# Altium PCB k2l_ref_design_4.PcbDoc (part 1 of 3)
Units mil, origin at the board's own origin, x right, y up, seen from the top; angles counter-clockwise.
Board outline 8000 x 6000 mil, 2 copper layers (Top Layer, Bottom Layer), stack 62 mil thick; 620 components, 466 nets, 2754 pads, 0 vias.
Unrouted connection lines stored in the file: 183.
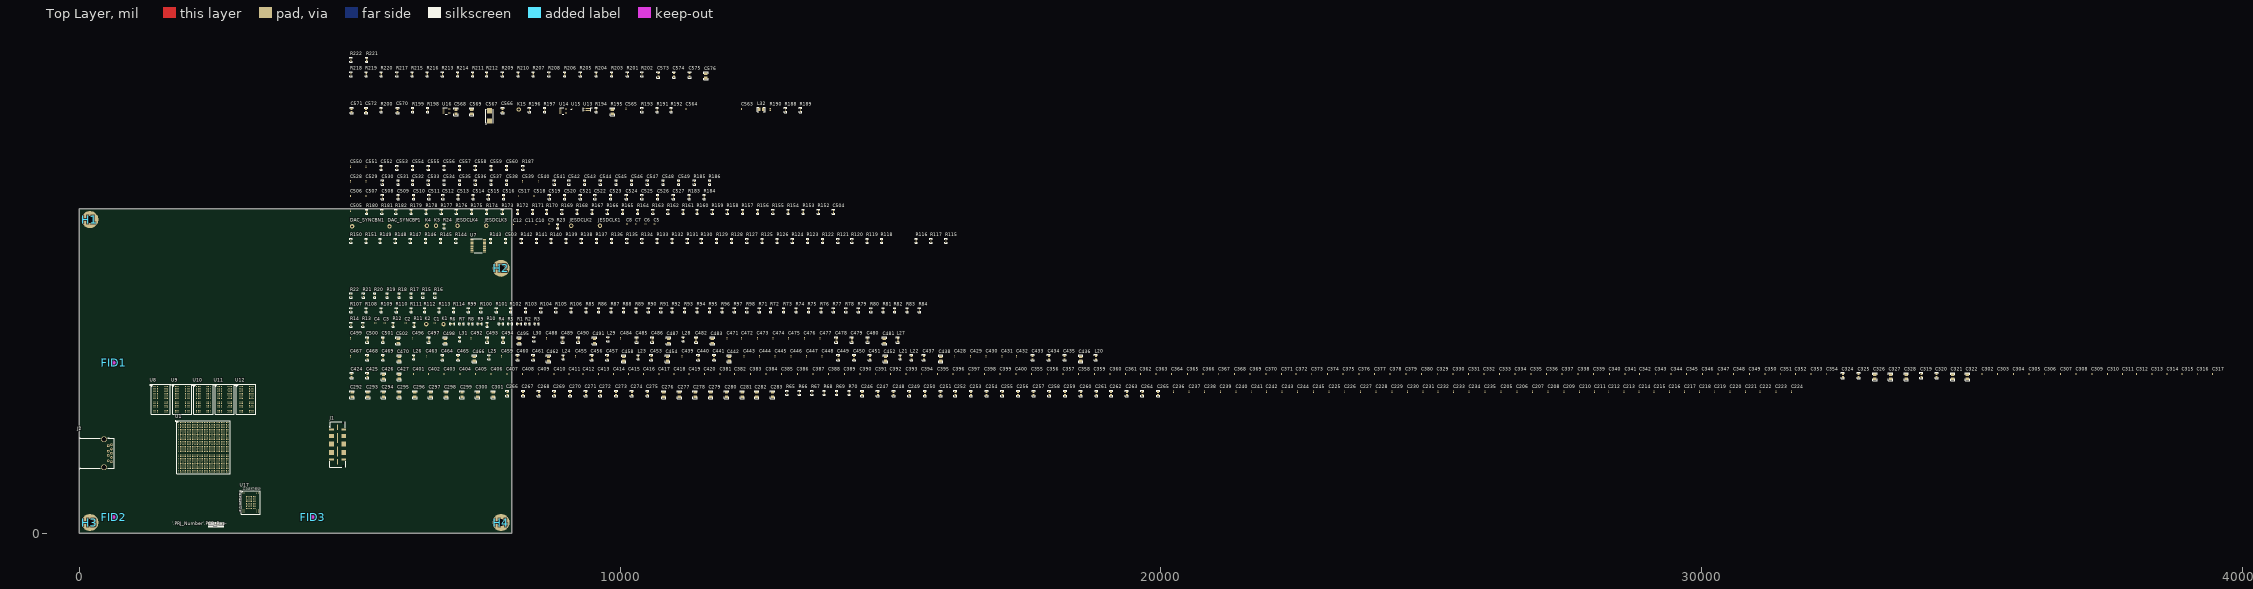
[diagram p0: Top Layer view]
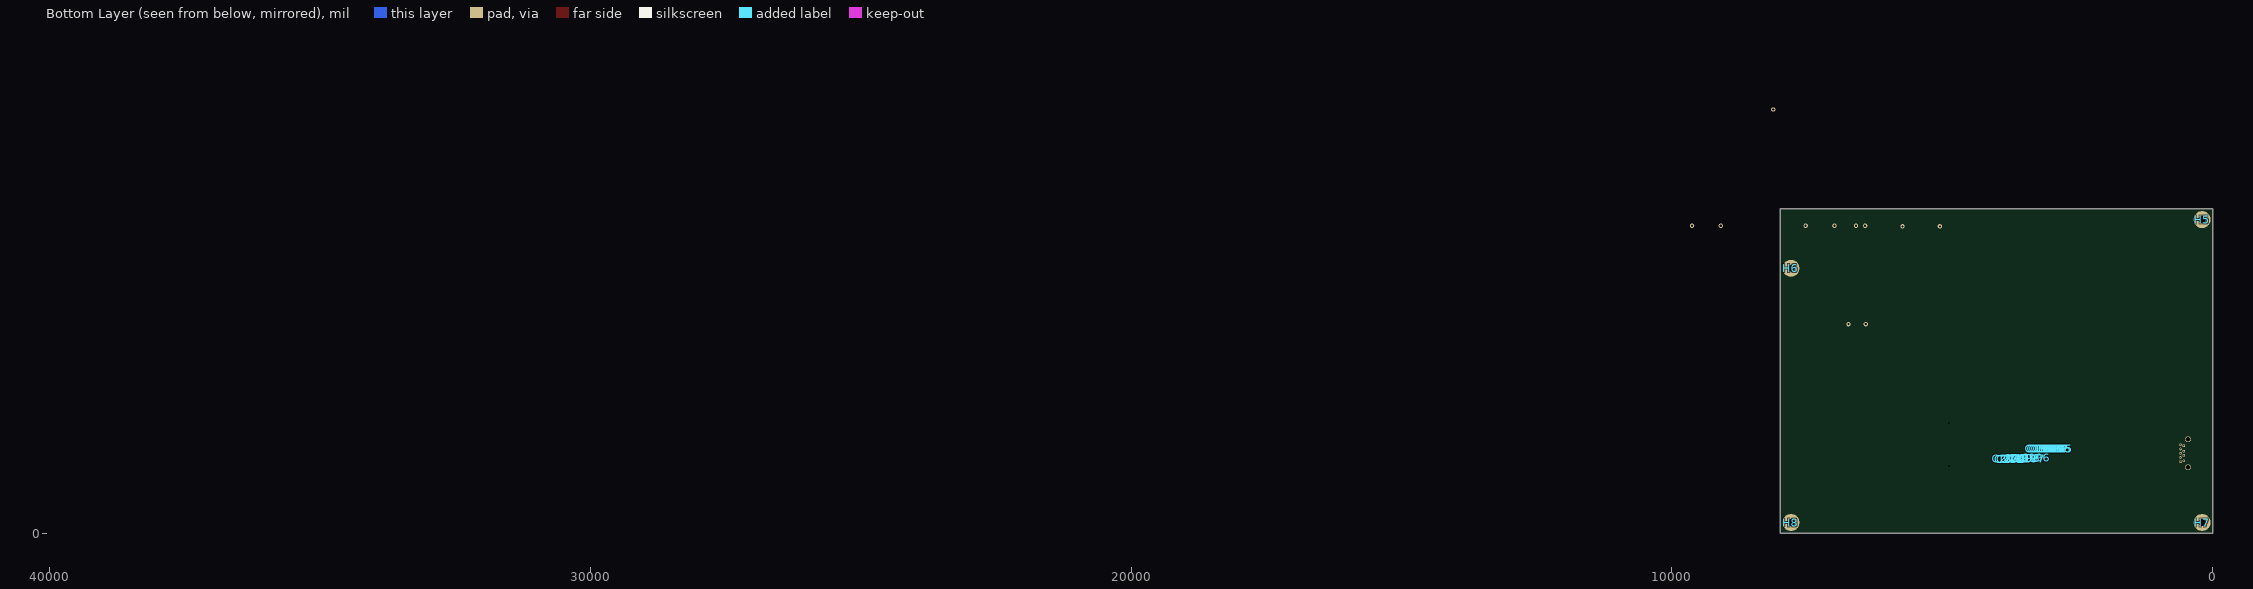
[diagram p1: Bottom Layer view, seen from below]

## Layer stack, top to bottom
Top Solder: solder mask 0.4, Solder Resist, Dk 3.5
Top Layer: signal copper 1.4
Dielectric1: core 59.2, FR-4, Dk 4.8
Bottom Layer: signal copper 1.4
Bottom Solder: solder mask 0.4, Solder Resist, Dk 3.5

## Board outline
0,0 0,6000 8000,6000 8000,0

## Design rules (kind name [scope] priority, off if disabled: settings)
AcuteAngle [All] p1: minimum=4.50000000000000E+0001 checktracksonly=FALSE
AssemblyTestPointUsage [All] p1: valid=2
BoardOutlineClearance BoardOutlineClearance_MountingHoles [OnCopper and InComponentClass('Mounting Holes')] p1: gap=40
BoardOutlineClearance BoardOutlineClearance_Poly [OnCopper and IsPoly] p2: gap=25
BoardOutlineClearance [OnCopper and Not InComponentClass('Logo') and not InComponentClass('FiducialMark') and not InRegion(1000,500,4000,800) and not InPoly] p3: gap=75
Clearance Clearance_Keepouts [((IsTrack Or IsArc) And Not InPoly) And IsFree and IsKeepOut vs ((IsTrack Or IsArc) And Not InPoly) And IsFree and IsKeepOut] p1: gap=0
Clearance Clearance_Poly [InPolygon] p2: gap=25
Clearance [All] p3: gap=7.87
ComponentClearance ComponentClearance_MountingHoles_FiducialMarks [InComponentClass('Mounting Holes') vs InComponentClass('FiducialMark')] p1: gap=50 collisioncheckmode=3 verticalgap=10 showdistances=FALSE
ComponentClearance ComponentClearance_Shunt [InComponentClass('Header') vs InComponentClass('Shunt')] p2: gap=0 collisioncheckmode=3 verticalgap=0 showdistances=FALSE
ComponentClearance ComponentClearance_Logo [InComponentClass('Logo')] p3: gap=50 collisioncheckmode=3 verticalgap=10 showdistances=FALSE
ComponentClearance ComponentClearance_ScrewToNut [(HasFootprint('NY PMS 440 0025 PH')) vs (HasFootprint('Keystone_1902C'))] p4: gap=5 collisioncheckmode=3 verticalgap=10 showdistances=FALSE
ComponentClearance ComponentClearance_MountingHoles [InComponentClass('Mounting Holes')] p5: gap=250 collisioncheckmode=3 verticalgap=100000 showdistances=FALSE
ComponentClearance ComponentClearance_SmallPassives [HasFootprint('0201*') or HasFootprint('0402*') or HasFootprint('0508') or HasFootprint('0603*') or HasFootprint('0612') or HasFootprint('0805*') or HasFootprint('0815*') or HasFootprint('0830*') or HasFootprint('1206*') or HasFootprint('1210*') or HasFootprint('1808*') or HasFootprint('1812*') or HasFootprint('1825*') or HasFootprint('2010*') or HasFootprint('2220*') or HasFootprint('2225*') or HasFootprint('2512*') or HasFootprint('2728*') or HasFootprint('3518*') vs HasFootprint('0201*') or HasFootprint('0402*') or HasFootprint('0508') or HasFootprint('0603*') or HasFootprint('0612') or HasFootprint('0805*') or HasFootprint('0815*') or HasFootprint('0830*') or HasFootprint('1206*') or HasFootprint('1210*') or HasFootprint('1808*') or HasFootprint('1812*') or HasFootprint('1825*') or HasFootprint('2010*') or HasFootprint('2220*') or HasFootprint('2225*') or HasFootprint('2512*') or HasFootprint('2728*') or HasFootprint('3518*')] p6: gap=14.96 collisioncheckmode=3 verticalgap=10 showdistances=FALSE
ComponentClearance ComponentClearance_THtoSMT [IsThruComponent vs IsSMTComponent] p7: gap=40 collisioncheckmode=3 verticalgap=30 showdistances=FALSE
ComponentClearance ComponentClearance_THtoTH [IsThruComponent vs IsThruComponent] p8: gap=30 collisioncheckmode=3 verticalgap=30 showdistances=FALSE
ComponentClearance [All] p9: gap=30 collisioncheckmode=3 verticalgap=10 showdistances=FALSE
DiffPairsRouting [All] p1: maxlimit=100 minlimit=10 mostfreqgap=10 toplayer_minwidth=15 toplayer_maxwidth=15 toplayer_prefwidth=15 bottomlayer_minwidth=15 bottomlayer_maxwidth=15 bottomlayer_prefwidth=15 maxuncoupledlength=1000
FabricationTestPointUsage TestPointUsage [All] p1: valid=2 allowmultiple=FALSE
FabricationTestpoint Testpoint [All] p1: side=3 testpointundercomponent=TRUE minsize=40 maxsize=100 preferedsize=60 minholesize=0 maxholesize=40 preferedholesize=32 testpointgrid=1 allowsidetop=TRUE allowsidebottom=TRUE usegrid=TRUE gridtolerance=0.01
FanoutControl Fanout_LCC [IsLCC] p1: bgadir=Out bgaviamode=Centered fanoutstyle=Auto fanoutdirection=Alternating viagrid=1 // Fanout_LCC (Default Rule)
FanoutControl Fanout_BGA [IsBGA] p2: bgadir=Out bgaviamode=Centered fanoutstyle=Auto fanoutdirection=Alternating viagrid=1 // Fanout_BGA (Default Rule)
FanoutControl Fanout_Default [All] p4: bgadir=Out bgaviamode=Centered fanoutstyle=Auto fanoutdirection=Alternating viagrid=1 // Fanout_Default (Default Rule)
FanoutControl Fanout_Small [(CompPinCount < 5)] p5: bgadir=Out bgaviamode=Centered fanoutstyle=Auto fanoutdirection=OutThenIn viagrid=1 // Fanout_Small (Default Rule)
HoleSize [All] p1: absolutevalues=TRUE maxlimit=251 minlimit=7.87 maxpercent=80.000 minpercent=20.000
MinimumAnnularRing MinimumAnnularRing_ThermalPadVias [IsVia and InAnyComponent] p1: minimumring=5.91
MinimumAnnularRing [All] p2: minimumring=8
MinimumSolderMaskSliver MinimumSolderMaskSliver_Logo [InComponentClass('Logo') vs InComponentClass('Logo')] p1: minsoldermaskwidth=0.7
MinimumSolderMaskSliver [All] p2: minsoldermaskwidth=3.94
PlaneConnect [All] p1: planeconnectstyle=Relief reliefexpansion=10 reliefentries=4 reliefconductorwidth=10 reliefairgap=10
PolygonConnect [All] p1: connectstyle=Relief reliefconductorwidth=10 reliefentries=4 polygonreliefangle="90 Angle" airgapwidth=10
RoutingVias ThermalPadVias [IsVia and InAnyComponent] p1: holewidth=7.87 width=19.68 viastyle="Through Hole" minholewidth=7.87 minwidth=19.68 maxholewidth=12.99 maxwidth=23.62
RoutingVias [All] p2: holewidth=16 width=34 viastyle="Through Hole" minholewidth=7.87 minwidth=26 maxholewidth=40 maxwidth=65
SilkToBoardRegionClearance [Not ((IsComment or IsDesignator) And (Hide <> 'False')) and not InRegion(1000,500,4000,800)] p1:
SilkToSilkClearance SilkToSilkClearance_Pb-FreeLogo [(HasFootprint('Pb-Free_Overlay_Medium') OR HasFootprint('Pb-Free_Overlay_Small')) vs (HasFootprint('Pb-Free_Overlay_Medium') OR HasFootprint('Pb-Free_Overlay_Small'))] p1: silktosilkclearance=0
SilkToSilkClearance [All] p2: silktosilkclearance=4
SilkToSolderMaskClearance SilkToComponentPadClearance [IsPad and InAnycomponent] p1: minsilkscreentomaskgap=5 clearancetoexposedcopper=TRUE
SilkToSolderMaskClearance "Silk to Solder Mask Opening" [All] p2: minsilkscreentomaskgap=4 clearancetoexposedcopper=FALSE
SolderMaskExpansion [All] p1: expansion=1.97
Width [All] p1: maxlimit=100 minlimit=6 preferedwidth=10 checkconnectedcopper=TRUE
15 further rules are at their usual default settings.

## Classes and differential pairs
component class "Mounting Holes": H1 H2 H3 H4
component class EVM_Hardware: FID1 FID2 FID3 H1 H2 H3 H4 H5 H6 H7 H8
component class FiducialMark: FID1 FID2 FID3
component class k2l_soc_01: U1
component class k2l_soc_02: C185 C186 C187 C188 C189 C190 C191 C192 C193 C194 C195 C196 C197 C198 C199 C200 C201 C202 C203 C204 C205 C206 C207 C208 C209 C210 C211 C212 C213 C214 C215 C216 C217 C218 C219 C220 C221 C222 C223 C224 C225 C226 C227 C228 C229 C230 C231 C232 C233 C234 C235 C236 C237 C238 C239 C240 C241 C242 C243 C244 C245 C246 C247 C248 C249 C250 C251 C252 C253 C254 C255 C256 C257 C258 C259 C260 C261 C262 C263 C264 C265 C266 C267 C268 C269 C270 C271 C272 C273 C274 C275 C276 C277 C278 C279 C280 C281 C282 C283 C284 C285 C286 C287 C288 C289 C290 C291 C292 C293 C294 C295 C296 C297 C298 C299 C300 C301 R65 R66 R67 R68 R69 R70
component class k2l_soc_03_1: C428 C429 C430 C431 C432 C433 C434 C435 C436 C437 C438 C439 C440 C441 C442 C443 C444 C445 C446 C447 C448 C449 C450 C451 C452 C453 C454 C455 C456 C457 C458 C459 C460 C461 C462 C463 C464 C465 C466 C467 C468 C469 C470 L20 L21 L22 L23 L24 L25 L26
component class k2l_soc_03: C302 C303 C304 C305 C306 C307 C308 C309 C310 C311 C312 C313 C314 C315 C316 C317 C318 C319 C320 C321 C322 C323 C324 C325 C326 C327 C328 C329 C330 C331 C332 C333 C334 C335 C336 C337 C338 C339 C340 C341 C342 C343 C344 C345 C346 C347 C348 C349 C350 C351 C352 C353 C354 C355 C356 C357 C358 C359 C360 C361 C362 C363 C364 C365 C366 C367 C368 C369 C370 C371 C372 C373 C374 C375 C376 C377 C378 C379 C380 C381 C382 C383 C384 C385 C386 C387 C388 C389 C390 C391 C392 C393 C394 C395 C396 C397 C398 C399 C400 C401 C402 C403 C404 C405 C406 C407 C408 C409 C410 C411 C412 C413 C414 C415 C416 C417 C418 C419 C420 C421 C422 C423 C424 C425 C426 C427
component class k2l_soc_04: C471 C472 C473 C474 C475 C476 C477 C478 C479 C480 C481 C482 C483 C484 C485 C486 C487 C488 C489 C490 C491 C492 C493 C494 C495 C496 C497 C498 C499 C500 C501 C502 L27 L28 L29 L30 L31
component class k2l_soc_05: C1 C2 C3 C4 K1 K2 R1 R2 R3 R4 R5 R6 R7 R8 R9 R10 R11 R12 R13 R14
component class k2l_soc_06_1: R15 R16 R17 R18 R19 R20 R21 R22
component class k2l_soc_06: R71 R72 R73 R74 R75 R76 R77 R78 R79 R80 R81 R82 R83 R84 R85 R86 R87 R88 R89 R90 R91 R92 R93 R94 R95 R96 R97 R98 R99 R100 R101 R102 R103 R104 R105 R106 R107 R108 R109 R110 R111 R112 R113 R114
component class k2l_soc_07: C503 J1 R115 R116 R117 R118 R119 R120 R121 R122 R123 R124 R125 R126 R127 R128 R129 R130 R131 R132 R133 R134 R135 R136 R137 R138 R139 R140 R141 R142 R143 R144 R145 R146 R147 R148 R149 R150 R151 U7
component class k2l_soc_08: C5 C6 C7 C8 C9 C10 C11 C12 DAC_SYNCBN1 DAC_SYNCBP1 JESDCLK1 JESDCLK2 JESDCLK3 JESDCLK4 K3 K4 R23 R24
component class k2l_soc_09_2: C506 C507 C508 C509 C510 C511 C512 C513 C514 C515 C516 C517 C518 C519 C520 C521 C522 C523 C524 C525 C526 C527 R183 R184 U8 U9
component class k2l_soc_09_3: C528 C529 C530 C531 C532 C533 C534 C535 C536 C537 C538 C539 C540 C541 C542 C543 C544 C545 C546 C547 C548 C549 R185 R186 U10 U11
component class k2l_soc_09_4: C550 C551 C552 C553 C554 C555 C556 C557 C558 C559 C560 R187 U12
component class k2l_soc_09: C504 C505 R152 R153 R154 R155 R156 R157 R158 R159 R160 R161 R162 R163 R164 R165 R166 R167 R168 R169 R170 R171 R172 R173 R174 R175 R176 R177 R178 R179 R180 R181 R182
component class k2l_soc_10: C561 C562 C563 C564 C565 C566 C567 C568 C569 C570 C571 C572 J2 K15 L32 R188 R189 R190 R191 R192 R193 R194 R195 R196 R197 R198 R199 R200 U13 U14 U15 U16
component class k2l_soc_13: C573 C574 C575 C576 R201 R202 R203 R204 R205 R206 R207 R208 R209 R210 R211 R212 R213 R214 R215 R216 R217 R218 R219 R220 U17
component class k2l_soc_14: R221 R222
net class K2L_DDR3A[15..0]: K2L_DDR3A0 K2L_DDR3A1 K2L_DDR3A2 K2L_DDR3A3 K2L_DDR3A4 K2L_DDR3A5 K2L_DDR3A6 K2L_DDR3A7 K2L_DDR3A8 K2L_DDR3A9 K2L_DDR3A10 K2L_DDR3A11 K2L_DDR3A12 K2L_DDR3A13 K2L_DDR3A14 K2L_DDR3A15
net class K2L_DDR3CB[7..0]: K2L_DDR3CB0 K2L_DDR3CB1 K2L_DDR3CB2 K2L_DDR3CB3 K2L_DDR3CB4 K2L_DDR3CB5 K2L_DDR3CB6 K2L_DDR3CB7
net class K2L_DDR3D[63..0]: K2L_DDR3D0 K2L_DDR3D1 K2L_DDR3D2 K2L_DDR3D3 K2L_DDR3D4 K2L_DDR3D5 K2L_DDR3D6 K2L_DDR3D7 K2L_DDR3D8 K2L_DDR3D9 K2L_DDR3D10 K2L_DDR3D11 K2L_DDR3D12 K2L_DDR3D13 K2L_DDR3D14 K2L_DDR3D15 K2L_DDR3D16 K2L_DDR3D17 K2L_DDR3D18 K2L_DDR3D19 K2L_DDR3D20 K2L_DDR3D21 K2L_DDR3D22 K2L_DDR3D23 K2L_DDR3D24 K2L_DDR3D25 K2L_DDR3D26 K2L_DDR3D27 K2L_DDR3D28 K2L_DDR3D29 K2L_DDR3D30 K2L_DDR3D31 K2L_DDR3D32 K2L_DDR3D33 K2L_DDR3D34 K2L_DDR3D35 K2L_DDR3D36 K2L_DDR3D37 K2L_DDR3D38 K2L_DDR3D39 K2L_DDR3D40 K2L_DDR3D41 K2L_DDR3D42 K2L_DDR3D43 K2L_DDR3D44 K2L_DDR3D45 K2L_DDR3D46 K2L_DDR3D47 K2L_DDR3D48 K2L_DDR3D49 K2L_DDR3D50 K2L_DDR3D51 K2L_DDR3D52 K2L_DDR3D53 K2L_DDR3D54 K2L_DDR3D55 K2L_DDR3D56 K2L_DDR3D57 K2L_DDR3D58 K2L_DDR3D59 K2L_DDR3D60 K2L_DDR3D61 K2L_DDR3D62 K2L_DDR3D63
net class K2L_DFEIO[17..0]: K2L_DFEIO0 K2L_DFEIO1 K2L_DFEIO2 K2L_DFEIO3 K2L_DFEIO4 K2L_DFEIO5 K2L_DFEIO6 K2L_DFEIO7 K2L_DFEIO8 K2L_DFEIO9 K2L_DFEIO10 K2L_DFEIO11 K2L_DFEIO12 K2L_DFEIO13 K2L_DFEIO14 K2L_DFEIO15 K2L_DFEIO16 K2L_DFEIO17
net class K2L_GPIO[16..0]: K2L_GPIO0 K2L_GPIO1 K2L_GPIO2 K2L_GPIO3 K2L_GPIO4 K2L_GPIO5 K2L_GPIO6 K2L_GPIO7 K2L_GPIO8 K2L_GPIO9 K2L_GPIO10 K2L_GPIO11 K2L_GPIO12 K2L_GPIO13 K2L_GPIO14 K2L_GPIO15 K2L_GPIO16 K2L_GPIO17 K2L_GPIO18 K2L_GPIO19 K2L_GPIO20 K2L_GPIO21 K2L_GPIO22 K2L_GPIO23 K2L_GPIO24 K2L_GPIO26 K2L_GPIO27 K2L_GPIO28 K2L_GPIO29 K2L_GPIO30 K2L_GPIO31 K2L_GPIO32
net class Undefined: GND K2L_DDR3RZQ0 K2L_DDR3RZQ1 K2L_DDR3RZQ2 K2L_DDR3VREF K2L_JESD_RXN0 K2L_JESD_RXN0_CAP K2L_JESD_RXN1 K2L_JESD_RXN1_CAP K2L_JESD_RXP0 K2L_JESD_RXP0_CAP K2L_JESD_RXP1 K2L_JESD_RXP1_CAP K2L_JESD_TXN0 K2L_JESD_TXN1 K2L_JESD_TXN2 K2L_JESD_TXN3 K2L_JESD_TXP0 K2L_JESD_TXP1 K2L_JESD_TXP2 K2L_JESD_TXP3 K2L_SERDES0_REF K2L_SERDES1_REF NetR195_2

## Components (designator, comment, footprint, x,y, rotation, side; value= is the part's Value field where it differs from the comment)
C1 "C0603X5R0J104K030BC" 0201 6578,3886 r0 top
C2 "C0603X5R0J104K030BC" 0201 6038,3886 r0 top
C3 "C0603X5R0J104K030BC" 0201 5648,3886 r0 top
C4 "C0603X5R0J104K030BC" 0201 5478,3886 r0 top
C5 "CL03A104KP3NNNC" 0201L 10638,5716 r0 top
C6 "CL03A104KP3NNNC" 0201L 10468,5716 r0 top
C7 "CL03A104KP3NNNC" 0201L 10298,5716 r0 top
C8 "CL03A104KP3NNNC" 0201L 10128,5716 r0 top
C9 "CL03A104KP3NNNC" 0201L 8688,5716 r0 top
C10 "CL03A104KP3NNNC" 0201L 8448,5696 r90 top
C11 "CL03A104KP3NNNC" 0201L 8248,5696 r90 top
C12 "CL03A104KP3NNNC" 0201L 8028,5696 r90 top
C185 "GRM033R70J103KA01D" 0201 2846.46,1562.99 r90 bottom
C186 "GRM033R70J103KA01D" 0201 2877.95,1562.99 r90 bottom
C187 "GRM033R70J103KA01D" 0201 2913.39,1562.99 r90 bottom
C188 "GRM033R70J103KA01D" 0201 2948.82,1562.99 r90 bottom
C189 "GRM033R70J103KA01D" 0201 2984.25,1562.99 r90 bottom
C190 "GRM033R70J103KA01D" 0201 3019.69,1562.99 r90 bottom
C191 "GRM033R70J103KA01D" 0201 3055.12,1562.99 r90 bottom
C192 "GRM033R70J103KA01D" 0201 3090.55,1562.99 r90 bottom
C193 "GRM033R70J103KA01D" 0201 3125.98,1562.99 r90 bottom
C194 "GRM033R70J103KA01D" 0201 3161.42,1562.99 r90 bottom
C195 "GRM033R70J103KA01D" 0201 3196.85,1562.99 r90 bottom
C196 "GRM033R70J103KA01D" 0201 3263.78,1396.26 r90 bottom
C197 "GRM033R70J103KA01D" 0201 3358.27,1376.57 r90 bottom
C198 "GRM033R70J103KA01D" 0201 3448.82,1384.45 r90 bottom
C199 "GRM033R70J103KA01D" 0201 3519.69,1384.45 r90 bottom
C200 "GRM033R70J103KA01D" 0201 3590.55,1392.32 r90 bottom
C201 "GRM033R70J103KA01D" 0201 3657.48,1376.57 r90 bottom
C202 "GRM033R70J103KA01D" 0201 3724.41,1372.64 r90 bottom
C203 "GRM033R70J103KA01D" 0201 3767.72,1368.7 r90 bottom
C204 "GRM033R70J103KA01D" 0201 3814.96,1380.51 r90 bottom
C205 "GRM033R60J223KE01D" 0201 26288,2616 r90 top
C206 "GRM033R60J223KE01D" 0201 26578,2616 r90 top
C207 "GRM033R60J223KE01D" 0201 26868,2616 r90 top
C208 "GRM033R60J223KE01D" 0201 27158,2616 r90 top
C209 "GRM033R60J223KE01D" 0201 27448,2616 r90 top
C210 "GRM033R60J223KE01D" 0201 27738,2616 r90 top
C211 "GRM033R60J223KE01D" 0201 28018,2616 r90 top
C212 "GRM033R60J223KE01D" 0201 28278,2616 r90 top
C213 "GRM033R60J223KE01D" 0201 28558,2616 r90 top
C214 "GRM033R60J223KE01D" 0201 28838,2616 r90 top
C215 "GRM033R60J223KE01D" 0201 29118,2616 r90 top
C216 "GRM033R60J223KE01D" 0201 29398,2616 r90 top
C217 "GRM033R60J223KE01D" 0201 29678,2616 r90 top
C218 "GRM033R60J223KE01D" 0201 29958,2616 r90 top
C219 "GRM033R60J223KE01D" 0201 30238,2616 r90 top
C220 "GRM033R60J223KE01D" 0201 30518,2616 r90 top
C221 "GRM033R60J223KE01D" 0201 30808,2616 r90 top
C222 "GRM033R60J223KE01D" 0201 31078,2616 r90 top
C223 "GRM033R60J223KE01D" 0201 31368,2616 r90 top
C224 "GRM033R60J223KE01D" 0201 31658,2616 r90 top
C225 "GRM033R60J473KE19D" 0201 23108,2616 r90 top
C226 "GRM033R60J473KE19D" 0201 23398,2616 r90 top
C227 "GRM033R60J473KE19D" 0201 23688,2616 r90 top
C228 "GRM033R60J473KE19D" 0201 23978,2616 r90 top
C229 "GRM033R60J473KE19D" 0201 24268,2616 r90 top
C230 "GRM033R60J473KE19D" 0201 24558,2616 r90 top
C231 "GRM033R60J473KE19D" 0201 24848,2616 r90 top
C232 "GRM033R60J473KE19D" 0201 25118,2616 r90 top
C233 "GRM033R60J473KE19D" 0201 25408,2616 r90 top
C234 "GRM033R60J473KE19D" 0201 25698,2616 r90 top
C235 "GRM033R60J473KE19D" 0201 25988,2616 r90 top
C236 "GRM033R60J104KE19D" 0201_033 20228,2616 r90 top
C237 "GRM033R60J104KE19D" 0201_033 20518,2616 r90 top
C238 "GRM033R60J104KE19D" 0201_033 20808,2616 r90 top
C239 "GRM033R60J104KE19D" 0201_033 21098,2616 r90 top
C240 "GRM033R60J104KE19D" 0201_033 21388,2616 r90 top
C241 "GRM033R60J104KE19D" 0201_033 21678,2616 r90 top
C242 "GRM033R60J104KE19D" 0201_033 21948,2616 r90 top
C243 "GRM033R60J104KE19D" 0201_033 22238,2616 r90 top
C244 "GRM033R60J104KE19D" 0201_033 22528,2616 r90 top
C245 "GRM033R60J104KE19D" 0201_033 22818,2616 r90 top
C246 "GRM188R61A224KA01D" 0603 14478,2586 r90 top
C247 "GRM188R61A224KA01D" 0603 14768,2586 r90 top
C248 "GRM188R61A224KA01D" 0603 15058,2586 r90 top
C249 "GRM188R61A224KA01D" 0603 15348,2586 r90 top
C250 "GRM188R61A224KA01D" 0603 15638,2586 r90 top
C251 "GRM188R61A224KA01D" 0603 15928,2586 r90 top
C252 "GRM188R61A224KA01D" 0603 16198,2586 r90 top
C253 "GRM188R61A224KA01D" 0603 16488,2586 r90 top
C254 "GRM188R61A224KA01D" 0603 16778,2586 r90 top
C255 "GRM188R61A224KA01D" 0603 17068,2586 r90 top
C256 "GRM188R61A474KA61D" 0603 17358,2586 r90 top
C257 "GRM188R61A474KA61D" 0603 17648,2586 r90 top
C258 "GRM188R61A474KA61D" 0603 17938,2586 r90 top
C259 "GRM188R61A474KA61D" 0603 18228,2586 r90 top
C260 "GRM188R61A474KA61D" 0603 18518,2586 r90 top
C261 "GRM188R61A474KA61D" 0603 18808,2586 r90 top
C262 "GRM188R61A474KA61D" 0603 19078,2586 r90 top
C263 "GRM188R61A474KA61D" 0603 19368,2586 r90 top
C264 "GRM188R61A474KA61D" 0603 19658,2586 r90 top
C265 "GRM188R61A474KA61D" 0603 19948,2586 r90 top
C266 "GRM188R70J105KA01D" 0603 7918,2586 r90 top
C267 "GRM188R70J105KA01D" 0603 8208,2586 r90 top
C268 "GRM188R70J105KA01D" 0603 8498,2586 r90 top
C269 "GRM188R70J105KA01D" 0603 8788,2586 r90 top
C270 "GRM188R70J105KA01D" 0603 9078,2586 r90 top
C271 "GRM188R70J105KA01D" 0603 9368,2586 r90 top
C272 "GRM188R70J105KA01D" 0603 9638,2586 r90 top
C273 "GRM188R70J105KA01D" 0603 9928,2586 r90 top
C274 "GRM188R70J105KA01D" 0603 10218,2586 r90 top
C275 "GRM188R70J105KA01D" 0603 10508,2586 r90 top
C276 "GRM21BF50J106ZE01L" 0805_HV 10808,2566 r90 top
C277 "GRM21BF50J106ZE01L" 0805_HV 11098,2566 r90 top
C278 "GRM21BF50J106ZE01L" 0805_HV 11388,2566 r90 top
C279 "GRM21BF50J106ZE01L" 0805_HV 11678,2566 r90 top
C280 "GRM21BF50J106ZE01L" 0805_HV 11968,2566 r90 top
C281 "GRM21BF50J106ZE01L" 0805_HV 12258,2566 r90 top
C282 "GRM21BF50J106ZE01L" 0805_HV 12528,2566 r90 top
C283 "GRM21BF50J106ZE01L" 0805_HV 12818,2566 r90 top
C292 "GRM21BC80G226ME39L" 0805_HV 5048,2566 r90 top
C293 "GRM21BC80G226ME39L" 0805_HV 5338,2566 r90 top
C294 "GRM21BC80G226ME39L" 0805_HV 5628,2566 r90 top
C295 "GRM21BC80G226ME39L" 0805_HV 5918,2566 r90 top
C296 "GRM21BC80G226ME39L" 0805_HV 6208,2566 r90 top
C297 "GRM21BR60J476ME15L" 0805_HV 6498,2566 r90 top
C298 "GRM21BR60J476ME15L" 0805_HV 6788,2566 r90 top
C299 "GRM21BR60J476ME15L" 0805_HV 7078,2566 r90 top
C300 "GRM21BR60J476ME15L" 0805_HV 7368,2566 r90 top
C301 "GRM21BR60J476ME15L" 0805_HV 7658,2566 r90 top
C302 "GRM033R60J104KE19D" 0201_033 35178,2946 r90 top
C303 "GRM033R60J104KE19D" 0201_033 35468,2946 r90 top
C304 "GRM033R60J104KE19D" 0201_033 35758,2946 r90 top
C305 "GRM033R60J104KE19D" 0201_033 36048,2946 r90 top
C306 "GRM033R60J104KE19D" 0201_033 36338,2946 r90 top
C307 "GRM033R60J103KA01D" 0201 36628,2946 r90 top
C308 "GRM033R60J103KA01D" 0201 36918,2946 r90 top
C309 "GRM033R60J103KA01D" 0201 37208,2946 r90 top
C310 "GRM033R60J103KA01D" 0201 37498,2946 r90 top
C311 "GRM033R60J103KA01D" 0201 37778,2946 r90 top
C312 "GRM033R71C102KA01D" 0201 38038,2946 r90 top
C313 "GRM033R71C102KA01D" 0201 38318,2946 r90 top
C314 "GRM033R71C102KA01D" 0201 38598,2946 r90 top
C315 "GRM033R71C102KA01D" 0201 38878,2946 r90 top
C316 "GRM033R71C102KA01D" 0201 39158,2946 r90 top
C317 "GRM033R71C102KA01D" 0201 39438,2946 r90 top
C319 "GRM188R70J105KA01D" 0603 34058,2916 r90 top
C320 "GRM188R70J105KA01D" 0603 34338,2916 r90 top
C321 "GRM21BR70J106KE76L" 0805_HV 34638,2896 r90 top
C322 "GRM21BR70J106KE76L" 0805_HV 34908,2896 r90 top
C324 "GRM188R70J105KA01D" 0603 32608,2916 r90 top
C325 "GRM188R70J105KA01D" 0603 32898,2916 r90 top
C326 "GRM21BR70J106KE76L" 0805_HV 33198,2896 r90 top
C327 "GRM21BR70J106KE76L" 0805_HV 33488,2896 r90 top
C328 "GRM21BR70J106KE76L" 0805_HV 33778,2896 r90 top
C329 "GRM033R60J104KE19D" 0201_033 25108,2946 r90 top
C330 "GRM033R60J104KE19D" 0201_033 25398,2946 r90 top
C331 "GRM033R60J104KE19D" 0201_033 25688,2946 r90 top
C332 "GRM033R60J104KE19D" 0201_033 25968,2946 r90 top
C333 "GRM033R60J104KE19D" 0201_033 26258,2946 r90 top
C334 "GRM033R60J104KE19D" 0201_033 26548,2946 r90 top
C335 "GRM033R60J104KE19D" 0201_033 26838,2946 r90 top
C336 "GRM033R60J104KE19D" 0201_033 27128,2946 r90 top
C337 "GRM033R60J104KE19D" 0201_033 27418,2946 r90 top
C338 "GRM033R60J104KE19D" 0201_033 27708,2946 r90 top
C339 "GRM033R60J104KE19D" 0201_033 27998,2946 r90 top
C340 "GRM033R60J104KE19D" 0201_033 28288,2946 r90 top
C341 "GRM033R60J104KE19D" 0201_033 28578,2946 r90 top
C342 "GRM033R60J104KE19D" 0201_033 28848,2946 r90 top
C343 "GRM033R60J104KE19D" 0201_033 29138,2946 r90 top
C344 "GRM033R60J104KE19D" 0201_033 29428,2946 r90 top
C345 "GRM033R60J104KE19D" 0201_033 29718,2946 r90 top
C346 "GRM033R60J104KE19D" 0201_033 30008,2946 r90 top
C347 "GRM033R60J104KE19D" 0201_033 30298,2946 r90 top
C348 "GRM033R60J104KE19D" 0201_033 30588,2946 r90 top
C349 "GRM033R60J104KE19D" 0201_033 30878,2946 r90 top
C350 "GRM033R60J104KE19D" 0201_033 31168,2946 r90 top
C351 "GRM033R60J104KE19D" 0201_033 31458,2946 r90 top
C352 "GRM033R60J104KE19D" 0201_033 31728,2946 r90 top
C353 "GRM033R60J104KE19D" 0201_033 32018,2946 r90 top
C354 "GRM033R60J104KE19D" 0201_033 32308,2946 r90 top
C355 "GRM033C80G223KE01D" 0201 17608,2946 r90 top
C356 "GRM033C80G223KE01D" 0201 17898,2946 r90 top
C357 "GRM033C80G223KE01D" 0201 18188,2946 r90 top
C358 "GRM033C80G223KE01D" 0201 18478,2946 r90 top
C359 "GRM033C80G223KE01D" 0201 18768,2946 r90 top
C360 "GRM033C80G223KE01D" 0201 19058,2946 r90 top
C361 "GRM033C80G223KE01D" 0201 19348,2946 r90 top
C362 "GRM033C80G223KE01D" 0201 19618,2946 r90 top
C363 "GRM033C80G223KE01D" 0201 19908,2946 r90 top
C364 "GRM033C80G223KE01D" 0201 20198,2946 r90 top
C365 "GRM033C80G223KE01D" 0201 20488,2946 r90 top
C366 "GRM033C80G223KE01D" 0201 20778,2946 r90 top
C367 "GRM033C80G223KE01D" 0201 21068,2946 r90 top
C368 "GRM033C80G223KE01D" 0201 21358,2946 r90 top
C369 "GRM033C80G223KE01D" 0201 21648,2946 r90 top
C370 "GRM033C80G223KE01D" 0201 21938,2946 r90 top
C371 "GRM033R60J103KA01D" 0201 22228,2946 r90 top
C372 "GRM033R60J103KA01D" 0201 22498,2946 r90 top
C373 "GRM033R60J103KA01D" 0201 22788,2946 r90 top
C374 "GRM033R60J103KA01D" 0201 23078,2946 r90 top
C375 "GRM033R60J103KA01D" 0201 23368,2946 r90 top
C376 "GRM033R60J103KA01D" 0201 23658,2946 r90 top
C377 "GRM033R60J103KA01D" 0201 23948,2946 r90 top
C378 "GRM033R60J103KA01D" 0201 24238,2946 r90 top
C379 "GRM033R60J103KA01D" 0201 24528,2946 r90 top
C380 "GRM033R60J103KA01D" 0201 24818,2946 r90 top
C381 "GRM033R60J104KE19D" 0201_033 11848,2946 r90 top
C382 "GRM033R60J104KE19D" 0201_033 12118,2946 r90 top
C383 "GRM033R60J104KE19D" 0201_033 12408,2946 r90 top
C384 "GRM033R60J104KE19D" 0201_033 12698,2946 r90 top
C385 "GRM033R60J104KE19D" 0201_033 12988,2946 r90 top
C386 "GRM033R60J104KE19D" 0201_033 13278,2946 r90 top
C387 "GRM033R60J104KE19D" 0201_033 13568,2946 r90 top
C388 "GRM033R60J104KE19D" 0201_033 13858,2946 r90 top
C389 "GRM033R60J104KE19D" 0201_033 14148,2946 r90 top
C390 "GRM033R60J104KE19D" 0201_033 14438,2946 r90 top
C391 "GRM033R60J104KE19D" 0201_033 14728,2946 r90 top
C392 "GRM033R60J104KE19D" 0201_033 14998,2946 r90 top
C393 "GRM033R60J104KE19D" 0201_033 15288,2946 r90 top
C394 "GRM033R60J104KE19D" 0201_033 15578,2946 r90 top
C395 "GRM033R60J104KE19D" 0201_033 15868,2946 r90 top
C396 "GRM033R60J104KE19D" 0201_033 16158,2946 r90 top
C397 "GRM033R60J104KE19D" 0201_033 16448,2946 r90 top
C398 "GRM033R60J104KE19D" 0201_033 16738,2946 r90 top
C399 "GRM033R60J104KE19D" 0201_033 17028,2946 r90 top
C400 "GRM033R60J104KE19D" 0201_033 17318,2946 r90 top
C401 "GRM033C80G223KE01D" 0201 6178,2946 r90 top
C402 "GRM033C80G223KE01D" 0201 6458,2946 r90 top
C403 "GRM033C80G223KE01D" 0201 6748,2946 r90 top
C404 "GRM033C80G223KE01D" 0201 7038,2946 r90 top
C405 "GRM033C80G223KE01D" 0201 7328,2946 r90 top
C406 "GRM033C80G223KE01D" 0201 7618,2946 r90 top
C407 "GRM033C80G223KE01D" 0201 7908,2946 r90 top
C408 "GRM033C80G223KE01D" 0201 8198,2946 r90 top
C409 "GRM033C80G223KE01D" 0201 8488,2946 r90 top
C410 "GRM033C80G223KE01D" 0201 8778,2946 r90 top
C411 "GRM033R60J103KA01D" 0201 9058,2946 r90 top
C412 "GRM033R60J103KA01D" 0201 9318,2946 r90 top
C413 "GRM033R60J103KA01D" 0201 9598,2946 r90 top
C414 "GRM033R60J103KA01D" 0201 9878,2946 r90 top
C415 "GRM033R60J103KA01D" 0201 10158,2946 r90 top
C416 "GRM033R60J103KA01D" 0201 10438,2946 r90 top
C417 "GRM033R60J103KA01D" 0201 10718,2946 r90 top
C418 "GRM033R60J103KA01D" 0201 10998,2946 r90 top
C419 "GRM033R60J103KA01D" 0201 11278,2946 r90 top
C420 "GRM033R60J103KA01D" 0201 11558,2946 r90 top
C424 "GRM188R70J105KA01D" 0603 5038,2916 r90 top
C425 "GRM188R70J105KA01D" 0603 5328,2916 r90 top
C426 "GRM21BR70J106KE76L" 0805_HV 5628,2896 r90 top
C427 "GRM21BR70J106KE76L" 0805_HV 5918,2896 r90 top
C428 "GRM033R60J103KA01D" 0201 16188,3276 r90 top
C429 "GRM033R60J103KA01D" 0201 16478,3276 r90 top
C430 "GRM033R60J103KA01D" 0201 16768,3276 r90 top
C431 "GRM033R60J103KA01D" 0201 17058,3276 r90 top
C432 "GRM033R60J103KA01D" 0201 17328,3276 r90 top
C433 "GRM188R70J104KA01D" 0603 17628,3246 r90 top
C434 "GRM188R70J104KA01D" 0603 17928,3246 r90 top
C435 "GRM188R70J105KA01D" 0603 18218,3246 r90 top
C436 "GRM21BF50J106ZE01L" 0805_HV 18518,3226 r90 top
C437 "GRM188R70J105KA01D" 0603 15618,3246 r90 top
C438 "GRM21BF50J106ZE01L" 0805_HV 15928,3226 r90 top
C439 "GRM033R60J103KA01D" 0201 11148,3276 r90 top
C440 "GRM188R70J104KA01D" 0603 11448,3246 r90 top
C441 "GRM188R70J105KA01D" 0603 11738,3246 r90 top
C442 "GRM21BF50J106ZE01L" 0805_HV 12018,3226 r90 top
C443 "GRM033R60J103KA01D" 0201 12288,3276 r90 top
C444 "GRM033R60J103KA01D" 0201 12578,3276 r90 top
C445 "GRM033R60J103KA01D" 0201 12868,3276 r90 top
C446 "GRM033R60J103KA01D" 0201 13158,3276 r90 top
C447 "GRM033R60J103KA01D" 0201 13448,3276 r90 top
C448 "GRM033R60J103KA01D" 0201 13738,3276 r90 top
C449 "GRM188R70J104KA01D" 0603 14038,3246 r90 top
C450 "GRM188R70J104KA01D" 0603 14328,3246 r90 top
C451 "GRM188R70J105KA01D" 0603 14618,3246 r90 top
C452 "GRM21BF50J106ZE01L" 0805_HV 14908,3226 r90 top
C453 "GRM188R70J105KA01D" 0603 10578,3246 r90 top
C454 "GRM21BF50J106ZE01L" 0805_HV 10878,3226 r90 top
C455 "GRM033R60J103KA01D" 0201 9178,3276 r90 top
C456 "GRM188R70J104KA01D" 0603 9478,3246 r90 top
C457 "GRM188R70J105KA01D" 0603 9768,3246 r90 top
C458 "GRM21BF50J106ZE01L" 0805_HV 10068,3226 r90 top
C459 "GRM033R60J103KA01D" 0201 7808,3276 r90 top
C460 "GRM188R70J104KA01D" 0603 8108,3246 r90 top
C461 "GRM188R70J105KA01D" 0603 8398,3246 r90 top
C462 "GRM21BF50J106ZE01L" 0805_HV 8678,3226 r90 top
C463 "GRM033R60J103KA01D" 0201 6418,3276 r90 top
C464 "GRM188R70J104KA01D" 0603 6718,3246 r90 top
C465 "GRM188R70J105KA01D" 0603 7008,3246 r90 top
C466 "GRM21BF50J106ZE01L" 0805_HV 7308,3226 r90 top
C467 "GRM033R60J103KA01D" 0201 5018,3276 r90 top
C468 "GRM188R70J104KA01D" 0603 5328,3246 r90 top
C469 "GRM188R70J105KA01D" 0603 5618,3246 r90 top
C470 "GRM21BF50J106ZE01L" 0805_HV 5918,3226 r90 top
C471 "GRM033R60J103KA01D" 0201 11978,3606 r90 top
C472 "GRM033R60J103KA01D" 0201 12248,3606 r90 top
C473 "GRM033R60J103KA01D" 0201 12538,3606 r90 top
C474 "GRM033R60J103KA01D" 0201 12828,3606 r90 top
C475 "GRM033R60J103KA01D" 0201 13118,3606 r90 top
C476 "GRM033R60J103KA01D" 0201 13408,3606 r90 top
C477 "GRM033R60J103KA01D" 0201 13698,3606 r90 top
C478 "GRM188R70J104KA01D" 0603 13998,3576 r90 top
C479 "GRM188R70J104KA01D" 0603 14288,3576 r90 top
C480 "GRM188R70J105KA01D" 0603 14578,3576 r90 top
C481 "GRM21BF50J106ZE01L" 0805_HV 14888,3556 r90 top
C482 "GRM188R70J105KA01D" 0603 11408,3576 r90 top
C483 "GRM21BF50J106ZE01L" 0805_HV 11708,3556 r90 top
C484 "GRM033R60J103KA01D" 0201 10008,3606 r90 top
C485 "GRM188R70J104KA01D" 0603 10308,3576 r90 top
C486 "GRM188R70J105KA01D" 0603 10598,3576 r90 top
C487 "GRM21BF50J106ZE01L" 0805_HV 10898,3556 r90 top
C488 "GRM033R60J103KA01D" 0201 8638,3606 r90 top
C489 "GRM188R70J104KA01D" 0603 8938,3576 r90 top
C490 "GRM188R70J105KA01D" 0603 9228,3576 r90 top
C491 "GRM21BF50J106ZE01L" 0805_HV 9528,3556 r90 top
C492 "GRM033R60J103KA01D" 0201 7248,3606 r90 top
C493 "GRM188R70J104KA01D" 0603 7548,3576 r90 top
C494 "GRM188R70J105KA01D" 0603 7838,3576 r90 top
C495 "GRM21BF50J106ZE01L" 0805_HV 8138,3556 r90 top
C496 "GRM033R60J103KA01D" 0201 6168,3606 r90 top
C497 "GRM188R70J105KA01D" 0603 6468,3576 r90 top
C498 "GRM21BF50J106ZE01L" 0805_HV 6768,3556 r90 top
C499 "GRM033R60J103KA01D" 0201 5018,3606 r90 top
C500 "GRM188R70J104KA01D" 0603 5328,3576 r90 top
C501 "GRM188R70J105KA01D" 0603 5618,3576 r90 top
C502 "GRM21BF50J106ZE01L" 0805_HV 5898,3556 r90 top
C503 "GRM152B30J104KE19" 0402 7888,5406 r90 top
C504 "GRM152B30J104KE19" 0402 13948,5946 r90 top
C505 "C0603X5R0J104K030BC" 0201 5018,5966 r90 top
C506 "C0603X5R0J104K030BC" 0201 5018,6236 r90 top
C507 "C0603X5R0J104K030BC" 0201 5308,6236 r90 top
C508 "GRM152B30J104KE19" 0402 5608,6216 r90 top
C509 "GRM152B30J104KE19" 0402 5898,6216 r90 top
C510 "GRM152B30J104KE19" 0402 6188,6216 r90 top
C511 "GRM152B30J104KE19" 0402 6468,6216 r90 top
C512 "GRM152B30J104KE19" 0402 6728,6216 r90 top
C513 "GRM152B30J104KE19" 0402 7008,6216 r90 top
C514 "GRM152B30J104KE19" 0402 7288,6216 r90 top
C515 "GRM152B30J104KE19" 0402 7568,6216 r90 top
C516 "GRM152B30J104KE19" 0402 7848,6216 r90 top
C517 "C0603X5R0J104K030BC" 0201 8128,6236 r90 top
C518 "C0603X5R0J104K030BC" 0201 8408,6236 r90 top
C519 "GRM152B30J104KE19" 0402 8698,6216 r90 top
C520 "GRM152B30J104KE19" 0402 8978,6216 r90 top
C521 "GRM152B30J104KE19" 0402 9268,6216 r90 top
C522 "GRM152B30J104KE19" 0402 9538,6216 r90 top
C523 "GRM152B30J104KE19" 0402 9828,6216 r90 top
C524 "GRM152B30J104KE19" 0402 10118,6216 r90 top
C525 "GRM152B30J104KE19" 0402 10408,6216 r90 top
C526 "GRM152B30J104KE19" 0402 10698,6216 r90 top
C527 "GRM152B30J104KE19" 0402 10988,6216 r90 top
C528 "C0603X5R0J104K030BC" 0201 5018,6506 r90 top
C529 "C0603X5R0J104K030BC" 0201 5308,6506 r90 top
C530 "GRM152B30J104KE19" 0402 5608,6486 r90 top
C531 "GRM152B30J104KE19" 0402 5898,6486 r90 top
C532 "GRM152B30J104KE19" 0402 6168,6486 r90 top
C533 "GRM152B30J104KE19" 0402 6458,6486 r90 top
C534 "GRM152B30J104KE19" 0402 6748,6486 r90 top
C535 "GRM152B30J104KE19" 0402 7038,6486 r90 top
C536 "GRM152B30J104KE19" 0402 7328,6486 r90 top
C537 "GRM152B30J104KE19" 0402 7618,6486 r90 top
C538 "GRM152B30J104KE19" 0402 7908,6486 r90 top
C539 "C0603X5R0J104K030BC" 0201 8198,6506 r90 top
C540 "C0603X5R0J104K030BC" 0201 8488,6506 r90 top
C541 "GRM152B30J104KE19" 0402 8788,6486 r90 top
C542 "GRM152B30J104KE19" 0402 9058,6486 r90 top
C543 "GRM152B30J104KE19" 0402 9348,6486 r90 top
C544 "GRM152B30J104KE19" 0402 9638,6486 r90 top
C545 "GRM152B30J104KE19" 0402 9928,6486 r90 top
C546 "GRM152B30J104KE19" 0402 10218,6486 r90 top
C547 "GRM152B30J104KE19" 0402 10508,6486 r90 top
C548 "GRM152B30J104KE19" 0402 10798,6486 r90 top
C549 "GRM152B30J104KE19" 0402 11088,6486 r90 top
C550 "C0603X5R0J104K030BC" 0201 5018,6776 r90 top
C551 "C0603X5R0J104K030BC" 0201 5308,6776 r90 top
C552 "GRM152B30J104KE19" 0402 5588,6756 r90 top
C553 "GRM152B30J104KE19" 0402 5878,6756 r90 top
C554 "GRM152B30J104KE19" 0402 6168,6756 r90 top
C555 "GRM152B30J104KE19" 0402 6458,6756 r90 top
C556 "GRM152B30J104KE19" 0402 6748,6756 r90 top
C557 "GRM152B30J104KE19" 0402 7038,6756 r90 top
C558 "GRM152B30J104KE19" 0402 7328,6756 r90 top
C559 "GRM152B30J104KE19" 0402 7618,6756 r90 top
C560 "GRM152B30J104KE19" 0402 7908,6756 r90 top
C563 "CL03A104KP3NNNC" 0201L 12248,7846 r90 top
C564 "CL03A104KP3NNNC" 0201L 11218,7846 r90 top
C565 "GRM033R60J103KA01D" 0201 10108,7846 r90 top
C566 "GRM188R70J105KA01D" 0603 7828,7816 r90 top
C567 "293D107X9010C2TE3" 6032-28 7588,7716 r90 top
C568 "GRM21BC80G226ME39L" 0805_HV 6968,7796 r90 top
C569 "GRM21BR60J476ME15L" 0805_HV 7258,7796 r90 top
C570 "GRM188R70J105KA01D" 0603 5888,7816 r90 top
C571 "GRM188R70J105KA01D" 0603 5038,7816 r90 top
C572 "GRM188R70J105KA01D" 0603 5308,7816 r90 top
C573 "GRM188R70J105KA01D" 0603 10708,8476 r90 top
C574 "GRM188R70J105KA01D" 0603 10998,8476 r90 top
C575 "GRM188R70J105KA01D" 0603 11288,8476 r90 top
C576 "GRM21BF50J106ZE01L" 0805_HV 11588,8456 r90 top
DAC_SYNCBN1 "TESTPOINT" TESTPOINT 5048,5676 r90 top
DAC_SYNCBP1 "TESTPOINT" TESTPOINT 5738,5676 r90 top
FID1 "Fiducial" Fiducial10-20 640,3150 r0 top
FID2 "Fiducial" Fiducial10-20 640,300 r0 top
FID3 "Fiducial" Fiducial10-20 4320,300 r0 top
H1 "NY PMS 440 0025 PH" "NY PMS 440 0025 PH" 200,5800 r0 top locked
H2 "NY PMS 440 0025 PH" "NY PMS 440 0025 PH" 7800,4900 r0 top locked
H3 "NY PMS 440 0025 PH" "NY PMS 440 0025 PH" 200,200 r0 top locked
H4 "NY PMS 440 0025 PH" "NY PMS 440 0025 PH" 7800,200 r0 top locked
H5 "1902C" Keystone_1902C 200,5800 r180 bottom locked
H6 "1902C" Keystone_1902C 7800,4900 r180 bottom locked
H7 "1902C" Keystone_1902C 200,200 r180 bottom locked
H8 "1902C" Keystone_1902C 7800,200 r180 bottom locked
J1 "QSH-030-01-L-D-A" Samtec_QSH-030-01-X-D-A 4779.53,1641.73 r0 top
J2 "GSB4111312HR" Amphenol_GSB4111312HR 460.63,1480.32 r270 top
JESDCLK1 "TESTPOINT" TESTPOINT 9628,5686 r90 top
JESDCLK2 "TESTPOINT" TESTPOINT 9098,5686 r90 top
JESDCLK3 "TESTPOINT" TESTPOINT 7528,5686 r90 top
JESDCLK4 "TESTPOINT" TESTPOINT 6998,5686 r90 top
K1 "TESTPOINT" TESTPOINT 6738,3866 r0 top
K2 "TESTPOINT" TESTPOINT 6418,3866 r0 top
K3 "TESTPOINT" TESTPOINT 6598,5686 r0 top
K4 "TESTPOINT" TESTPOINT 6428,5686 r0 top
K15 "TESTPOINT" TESTPOINT 8128,7836 r0 top
L20 "BLM18SG121TN1D" 0603 18798,3246 r90 top
L21 "BLM15AG121SN1D" 0402 15178,3256 r90 top
L22 "BLM18SG121TN1D" 0603 15388,3246 r90 top
L23 "BLM15AG121SN1D" 0402 10338,3256 r90 top
L24 "BLM15AG121SN1D" 0402 8948,3256 r90 top
L25 "BLM15AG121SN1D" 0402 7578,3256 r90 top
L26 "BLM15AG121SN1D" 0402 6188,3256 r90 top
L27 "BLM18SG121TN1D" 0603 15138,3576 r90 top
L28 "BLM15AG121SN1D" 0402 11168,3586 r90 top
L29 "BLM15AG121SN1D" 0402 9778,3586 r90 top
L30 "BLM15AG121SN1D" 0402 8408,3586 r90 top
L31 "BLM15AG121SN1D" 0402 7038,3586 r90 top
L32 "MPZ2012S300AT000" 0805_HV 12608,7836 r0 top
R1 "CRCW04024K75FKED" 0402 8138,3876 r0 top
R2 "CRCW04024K75FKED" 0402 8288,3876 r0 top
R3 "CRCW04024K75FKED" 0402 8458,3876 r0 top
R4 "CRCW04021K00FKED" 0402 7798,3876 r0 top
R5 "CRCW04021K00FKED" 0402 7968,3876 r0 top
R6 "CRCW04021K00FKED" 0402 6898,3876 r0 top
R7 "CRCW04021K00FKED" 0402 7068,3876 r0 top
R8 "CRCW04021K00FKED" 0402 7238,3876 r0 top
R9 "CRCW04021K00FKED" 0402 7408,3876 r0 top
R10 "CRCW04021K00FKED" 0402 7548,3856 r90 top
R11 "CRCW040210R0FKED" 0402 6198,3856 r90 top
R12 "CRCW04021K00FKED" 0402 5808,3856 r90 top
R13 "CRCW04021K00FKED" 0402 5248,3856 r90 top
R14 "CRCW04021K00FKED" 0402 5028,3856 r90 top
R15 "CRCW04024K75FKED" 0402 6358,4396 r90 top
R16 "CRCW04024K75FKED" 0402 6578,4396 r90 top
R17 "CRCW040210R0FKED" 0402 6138,4396 r90 top
R18 "CRCW040210R0FKED" 0402 5918,4396 r90 top
R19 "CRCW040210R0FKED" 0402 5698,4396 r90 top
R20 "CRCW040210R0FKED" 0402 5468,4396 r90 top
R21 "CRCW040210R0FKED" 0402 5258,4396 r90 top
R22 "CRCW040210R0FKED" 0402 5028,4396 r90 top
R23 "CRCW04023K00JNED" 0402 8848,5676 r90 top
R24 "CRCW04023K00JNED" 0402 6748,5676 r90 top
R65 "CRCW04024K75FKED" 0402 13088,2596 r90 top
R66 "CRCW04024K75FKED" 0402 13318,2596 r90 top
R67 "CRCW04024K75FKED" 0402 13548,2596 r90 top
R68 "CRCW04024K75FKED" 0402 13778,2596 r90 top
R69 "CRCW04024K75FKED" 0402 14008,2596 r90 top
R70 "CRCW04024K75FKED" 0402 14238,2596 r90 top
R71 "CRCW04024K75FKED" 0402 12578,4126 r90 top
R72 "CRCW04024K75FKED" 0402 12788,4126 r90 top
R73 "CRCW04024K75FKED" 0402 13028,4126 r90 top
R74 "CRCW04024K75FKED" 0402 13258,4126 r90 top
R75 "CRCW04024K75FKED" 0402 13488,4126 r90 top
R76 "CRCW04024K75FKED" 0402 13718,4126 r90 top
R77 "CRCW04024K75FKED" 0402 13948,4126 r90 top
R78 "CRCW04024K75FKED" 0402 14178,4126 r90 top
R79 "CRCW04024K75FKED" 0402 14408,4126 r90 top
R80 "CRCW04024K75FKED" 0402 14638,4126 r90 top
R81 "CRCW04024K75FKED" 0402 14868,4126 r90 top
R82 "CRCW04024K75FKED" 0402 15078,4126 r90 top
R83 "CRCW04024K75FKED" 0402 15308,4126 r90 top
R84 "CRCW04024K75FKED" 0402 15538,4126 r90 top
R85 "CRCW04021K00FKED" 0402 9378,4126 r90 top
R86 "CRCW04021K00FKED" 0402 9608,4126 r90 top
R87 "CRCW04021K00FKED" 0402 9838,4126 r90 top
R88 "CRCW04021K00FKED" 0402 10068,4126 r90 top
R89 "CRCW04021K00FKED" 0402 10298,4126 r90 top
R90 "CRCW04021K00FKED" 0402 10528,4126 r90 top
R91 "CRCW04021K00FKED" 0402 10758,4126 r90 top
R92 "CRCW04021K00FKED" 0402 10968,4126 r90 top
R93 "CRCW04021K00FKED" 0402 11198,4126 r90 top
R94 "CRCW04021K00FKED" 0402 11428,4126 r90 top
R95 "CRCW04021K00FKED" 0402 11658,4126 r90 top
R96 "CRCW04021K00FKED" 0402 11888,4126 r90 top
R97 "CRCW04021K00FKED" 0402 12118,4126 r90 top
R98 "CRCW04021K00FKED" 0402 12348,4126 r90 top
R99 "CRCW04024K75FKED" 0402 7198,4126 r90 top
R100 "CRCW04024K75FKED" 0402 7428,4126 r90 top
R101 "CRCW04024K75FKED" 0402 7718,4126 r90 top
R102 "CRCW04024K75FKED" 0402 7978,4126 r90 top
R103 "CRCW04024K75FKED" 0402 8258,4126 r90 top
R104 "CRCW04024K75FKED" 0402 8538,4126 r90 top
R105 "CRCW04024K75FKED" 0402 8818,4126 r90 top
R106 "CRCW04024K75FKED" 0402 9098,4126 r90 top
R107 "CRCW04021K00FKED" 0402 5028,4126 r90 top
R108 "CRCW04021K00FKED" 0402 5308,4126 r90 top
R109 "CRCW04021K00FKED" 0402 5588,4126 r90 top
R110 "CRCW04021K00FKED" 0402 5868,4126 r90 top
R111 "CRCW04021K00FKED" 0402 6138,4126 r90 top
R112 "CRCW04021K00FKED" 0402 6388,4126 r90 top
R113 "CRCW04021K00FKED" 0402 6658,4126 r90 top
R114 "CRCW04021K00FKED" 0402 6928,4126 r90 top
R115 "CRCW04024K75FKED" 0402 16028,5406 r90 top
R116 "CRCW0402100RFKED" 0402 15478,5406 r90 top
R117 "CRCW0402100RFKED" 0402 15748,5406 r90 top
R118 "CRCW040210R0FKED" 0402 14838,5406 r90 top
R119 "CRCW040210R0FKED" 0402 14568,5406 r90 top
R120 "CRCW040210R0FKED" 0402 14288,5406 r90 top
R121 "CRCW040210R0FKED" 0402 14028,5406 r90 top
R122 "CRCW040210R0FKED" 0402 13748,5406 r90 top
R123 "CRCW04024K75FKED" 0402 13468,5406 r90 top
R124 "CRCW040210R0FKED" 0402 13188,5406 r90 top
R125 "CRCW040210R0FKED" 0402 12628,5406 r90 top
R126 "CRCW040210R0FKED" 0402 12908,5406 r90 top
R127 "CRCW040210R0FKED" 0402 12348,5406 r90 top
R128 "CRCW040210R0FKED" 0402 12068,5406 r90 top
R129 "CRCW040210R0FKED" 0402 11788,5406 r90 top
R130 "CRCW040210R0FKED" 0402 11508,5406 r90 top
R131 "CRCW040210R0FKED" 0402 11248,5406 r90 top
R132 "CRCW040210R0FKED" 0402 10968,5406 r90 top
R133 "CRCW040210R0FKED" 0402 10688,5406 r90 top
R134 "CRCW040210R0FKED" 0402 10408,5406 r90 top
R135 "CRCW040210R0FKED" 0402 10128,5406 r90 top
R136 "CRCW040210R0FKED" 0402 9848,5406 r90 top
R137 "CRCW040210R0FKED" 0402 9568,5406 r90 top
R138 "CRCW040210R0FKED" 0402 9288,5406 r90 top
R139 "CRCW040210R0FKED" 0402 9008,5406 r90 top
R140 "CRCW040210R0FKED" 0402 8728,5406 r90 top
R141 "CRCW040210R0FKED" 0402 8458,5406 r90 top
R142 "CRCW040210R0FKED" 0402 8178,5406 r90 top
R143 "CRCW040210R0FKED" 0402 7608,5406 r90 top
R144 "CRCW040210R0FKED" 0402 6968,5406 r90 top
R145 "CRCW040210R0FKED" 0402 6688,5406 r90 top
R146 "CRCW040210R0FKED" 0402 6408,5406 r90 top
R147 "CRCW040210R0FKED" 0402 6128,5406 r90 top
R148 "CRCW040210R0FKED" 0402 5848,5406 r90 top
R149 "CRCW040210R0FKED" 0402 5568,5406 r90 top
R150 "CRCW04024K75FKED" 0402 5028,5406 r90 top
R151 "CRCW040210R0FKED" 0402 5308,5406 r90 top
R152 "CRCW040239R2FKED" 0402 13668,5946 r90 top
R153 "CRCW040239R2FKED" 0402 13388,5946 r90 top
R154 "CRCW040239R2FKED" 0402 13108,5946 r90 top
R155 "CRCW040239R2FKED" 0402 12828,5946 r90 top
R156 "CRCW040239R2FKED" 0402 12548,5946 r90 top
R157 "CRCW040239R2FKED" 0402 12268,5946 r90 top
R158 "CRCW040239R2FKED" 0402 11988,5946 r90 top
R159 "CRCW040239R2FKED" 0402 11708,5946 r90 top
R160 "CRCW040239R2FKED" 0402 11428,5946 r90 top
R161 "CRCW040239R2FKED" 0402 11168,5946 r90 top
R162 "CRCW040239R2FKED" 0402 10888,5946 r90 top
R163 "CRCW040239R2FKED" 0402 10608,5946 r90 top
R164 "CRCW040239R2FKED" 0402 10328,5946 r90 top
R165 "CRCW040239R2FKED" 0402 10048,5946 r90 top
R166 "CRCW040239R2FKED" 0402 9768,5946 r90 top
R167 "CRCW040239R2FKED" 0402 9488,5946 r90 top
R168 "CRCW040239R2FKED" 0402 9208,5946 r90 top
R169 "CRCW040239R2FKED" 0402 8928,5946 r90 top
R170 "CRCW040239R2FKED" 0402 8648,5946 r90 top
R171 "CRCW040239R2FKED" 0402 8388,5946 r90 top
R172 "CRCW040239R2FKED" 0402 8108,5946 r90 top
R173 "CRCW040239R2FKED" 0402 7828,5946 r90 top
R174 "CRCW040239R2FKED" 0402 7538,5946 r90 top
R175 "CRCW040239R2FKED" 0402 7258,5946 r90 top
R176 "CRCW040239R2FKED" 0402 6978,5946 r90 top
R177 "CRCW040239R2FKED" 0402 6698,5946 r90 top
R178 "CRCW040239R2FKED" 0402 6418,5946 r90 top
R179 "CRCW040239R2FKED" 0402 6138,5946 r90 top
R180 "CRCW0402240RJNED" 0402 5318,5946 r90 top
R181 "CRCW0402240RJNED" 0402 5598,5946 r90 top
R182 "CRCW0402240RJNED" 0402 5858,5946 r90 top
R183 "CRCW0402240RJNED" 0402 11278,6216 r90 top
R184 "CRCW0402240RJNED" 0402 11558,6216 r90 top
R185 "CRCW0402240RJNED" 0402 11378,6486 r90 top
R186 "CRCW0402240RJNED" 0402 11658,6486 r90 top
R187 "CRCW0402240RJNED" 0402 8208,6756 r90 top
R188 "CRCW04021K00FKED" 0402 13058,7826 r90 top
R189 "CRCW04021K00FKED" 0402 13338,7826 r90 top
R190 "ERJ-1GEF1000C" 0201M 12778,7836 r90 top
R191 "CRCW04021K00FKED" 0402 10688,7826 r90 top
R192 "CRCW04021K00FKED" 0402 10948,7826 r90 top
R193 "CRCW04020000Z0ED" 0402 10408,7826 r90 top
R194 "CRCW04021K00FKED" 0402 9558,7826 r90 top
R195 "RG2012P-201-B-T5" 0805_HV 9858,7796 r90 top
R196 "CRCW04024K75FKED" 0402 8328,7826 r90 top
R197 "CRCW04024K75FKED" 0402 8608,7826 r90 top
R198 "CRCW04020000Z0ED" 0402 6448,7826 r90 top
R199 "CRCW04021K00FKED" 0402 6168,7826 r90 top
R200 "CRCW04020000Z0ED" 0402 5588,7826 r90 top
R201 "CRCW040210R0FKED" 0402 10138,8486 r90 top
R202 "CRCW040210R0FKED" 0402 10408,8486 r90 top
R203 "CRCW040210R0FKED" 0402 9848,8486 r90 top
R204 "CRCW040210R0FKED" 0402 9558,8486 r90 top
R205 "CRCW040210R0FKED" 0402 9268,8486 r90 top
R206 "CRCW040210R0FKED" 0402 8978,8486 r90 top
R207 "CRCW040210R0FKED" 0402 8398,8486 r90 top
R208 "CRCW040210R0FKED" 0402 8688,8486 r90 top
R209 "CRCW040210R0FKED" 0402 7828,8486 r90 top
R210 "CRCW040210R0FKED" 0402 8118,8486 r90 top
R211 "CRCW040210R0FKED" 0402 7278,8486 r90 top
R212 "CRCW040210R0FKED" 0402 7538,8486 r90 top
R213 "CRCW04024K75FKED" 0402 6718,8486 r90 top
R214 "CRCW040210R0FKED" 0402 6998,8486 r90 top
R215 "CRCW04024K75FKED" 0402 6158,8486 r90 top
R216 "CRCW04024K75FKED" 0402 6438,8486 r90 top
R217 "CRCW040210R0FKED" 0402 5878,8486 r90 top
R218 "CRCW040210R0FKED" 0402 5028,8486 r90 top
R219 "CRCW04024K75FKED" 0402 5308,8486 r90 top
R220 "CRCW04024K75FKED" 0402 5588,8486 r90 top
R221 "CRCW04023K00JNED" 0402 5318,8756 r90 top
R222 "CRCW04023K00JNED" 0402 5028,8756 r90 top
U1 "TCI6630K2L" BGA900C80P30X30_2500X2500X355 2299.21,1590.55 r0 top
U7 "SN74LVC244APW" PW0020A_N 7378,5316 r0 top
U8 "MT41K256M16HA-125" MICT-HA-96 1511.81,2476.38 r0 top
U9 "MT41K256M16HA-125" MICT-HA-96 1905.51,2476.38 r0 top
U10 "MT41K256M16HA-125" MICT-HA-96 2299.21,2476.38 r0 top
U11 "MT41K256M16HA-125" MICT-HA-96 2692.91,2476.38 r0 top
U12 "MT41K256M16HA-125" MICT-HA-96 3086.61,2476.38 r0 top
U13 "SP3012-06UTG" UDFN-14 9448,7856 r0 top
U14 "TPS2065CDBVR" DBV0005A_N 8948,7806 r0 top
U15 "TPS22913BYZVR" YZV0004ADAD 9118,7856 r90 top
U16 "SN74LVC1G07DBVR" DBV0005A_N 6788,7806 r0 top
U17 "MT29F16G08ADBCAH4:C" VBGA63_NANDx8 3173.23,570.87 r0 top

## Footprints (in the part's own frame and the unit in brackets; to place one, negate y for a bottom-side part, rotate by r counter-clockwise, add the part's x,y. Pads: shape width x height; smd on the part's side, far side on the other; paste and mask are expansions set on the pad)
0201 [mm] "Data from Kemet datasheet CC101_COM dated 7/28/11"
  rect 0.46x0.42 smd mask+0.048: 1(-0.33,0) 2(0.33,0)
  body extent -0.31,-0.16 0.31,0.16, height 0.26
0201_033 [mm] "SMD, 2-Leads, Height 0.33mm"
  rect 0.46x0.42 smd mask+0.048: 1(-0.33,0) 2(0.33,0)
  body extent -0.31,-0.16 0.31,0.16, height 0.33
0201L [mm] "Data from Kemet datasheet CC101_COM dated 7/28/11"
  rect 0.36x0.32 smd mask+0.048: 1(-0.28,0) 2(0.28,0)
  body extent -0.31,-0.16 0.31,0.16, height 0.26
0201M [mm] "Data from Kemet datasheet CC101_COM dated 7/28/11"
  rect 0.56x0.52 smd mask+0.048: 1(-0.38,0) 2(0.38,0)
  body extent -0.31,-0.16 0.31,0.16, height 0.26
0402 [mm] "0402 from SM-752 data"
  rect 0.8x0.6 smd: 1(-0.6,0) 2(0.6,0)
  silkscreen extent -1.22,-0.52 1.22,0.52, body extent -0.55,-0.3 0.55,0.3, height 0.6
0603 [mm] "0603 from SM-752 data"
  rect 1x0.95 smd: 1(-0.8,0) 2(0.8,0)
  silkscreen extent -1.52,-0.69 1.52,0.69, body extent -0.87,-0.47 0.87,0.47, height 1
0805_HV [mil] "0805 with 30mil clearance between pads"
  rect 50x63 smd: 1(-40,0) 2(40,0)
  silkscreen extent -74,-40 74,40, body extent -43,-29 43,29, height 57
6032-28 [mm] "Medium Density IPC based on Vishay Sprague 293D datasheet."
  rect 2.55x2.3 smd: 1(-2.375,0) 2(2.375,0)
  silkscreen extent -3.96,-1.75 3.2,1.82, body extent -3.15,-1.75 3.15,1.75, height 2.8
Amphenol_GSB4111312HR [mm] "Connector, Receptacle, USB 3.1 Type A, R/A, TH"
  rect 1.2x1.2 hole 0.7: 1(-3.5,2)
  round 1.2 hole 0.7: 2(-1,2) 3(1,2) 4(3.5,2) 5(4,3.5) 6(2,3.5) 7(0,3.5) 8(-2,3.5) 9(-4,3.5)
  round 2.8 hole 2.3: S1(-6.57,0) S2(6.57,0)
  silkscreen extent -7.25,-11.63 7.2,4.72, body extent -7.2,-11.78 7.2,4.72, height 7.74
